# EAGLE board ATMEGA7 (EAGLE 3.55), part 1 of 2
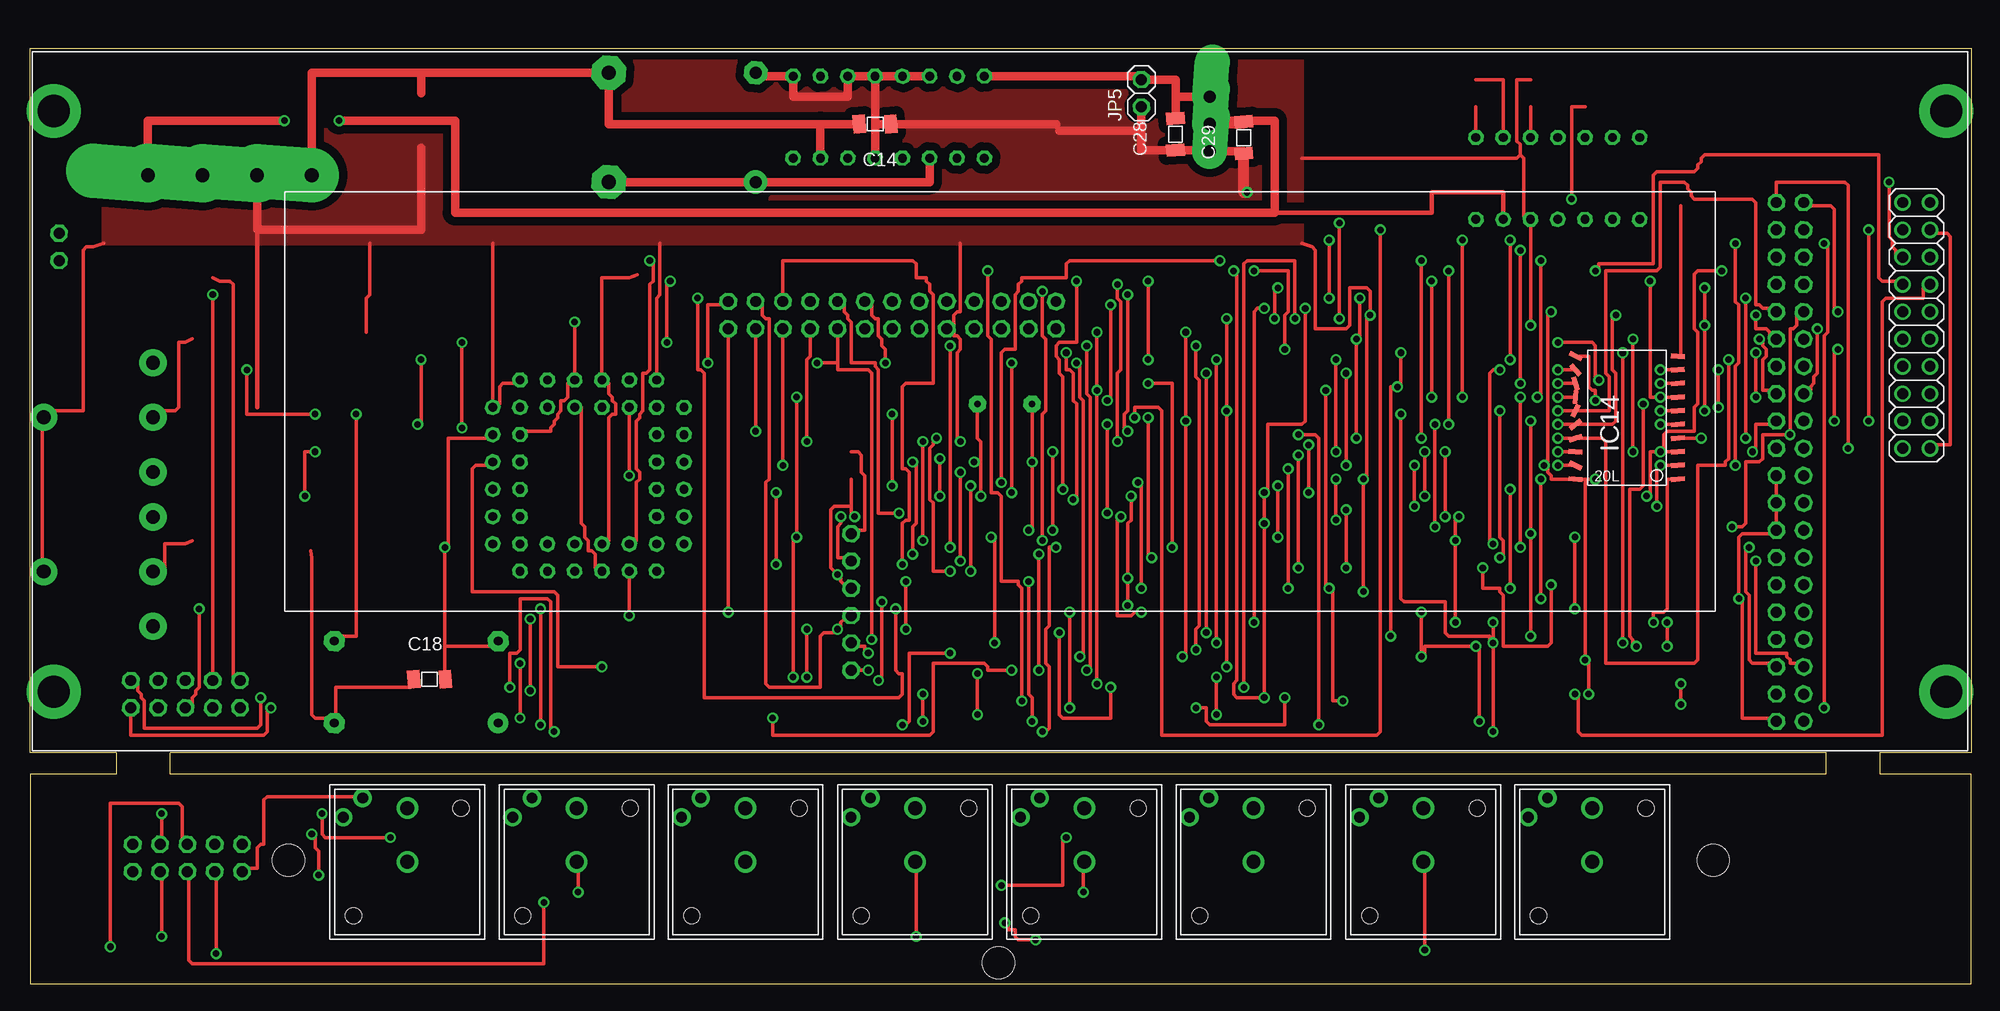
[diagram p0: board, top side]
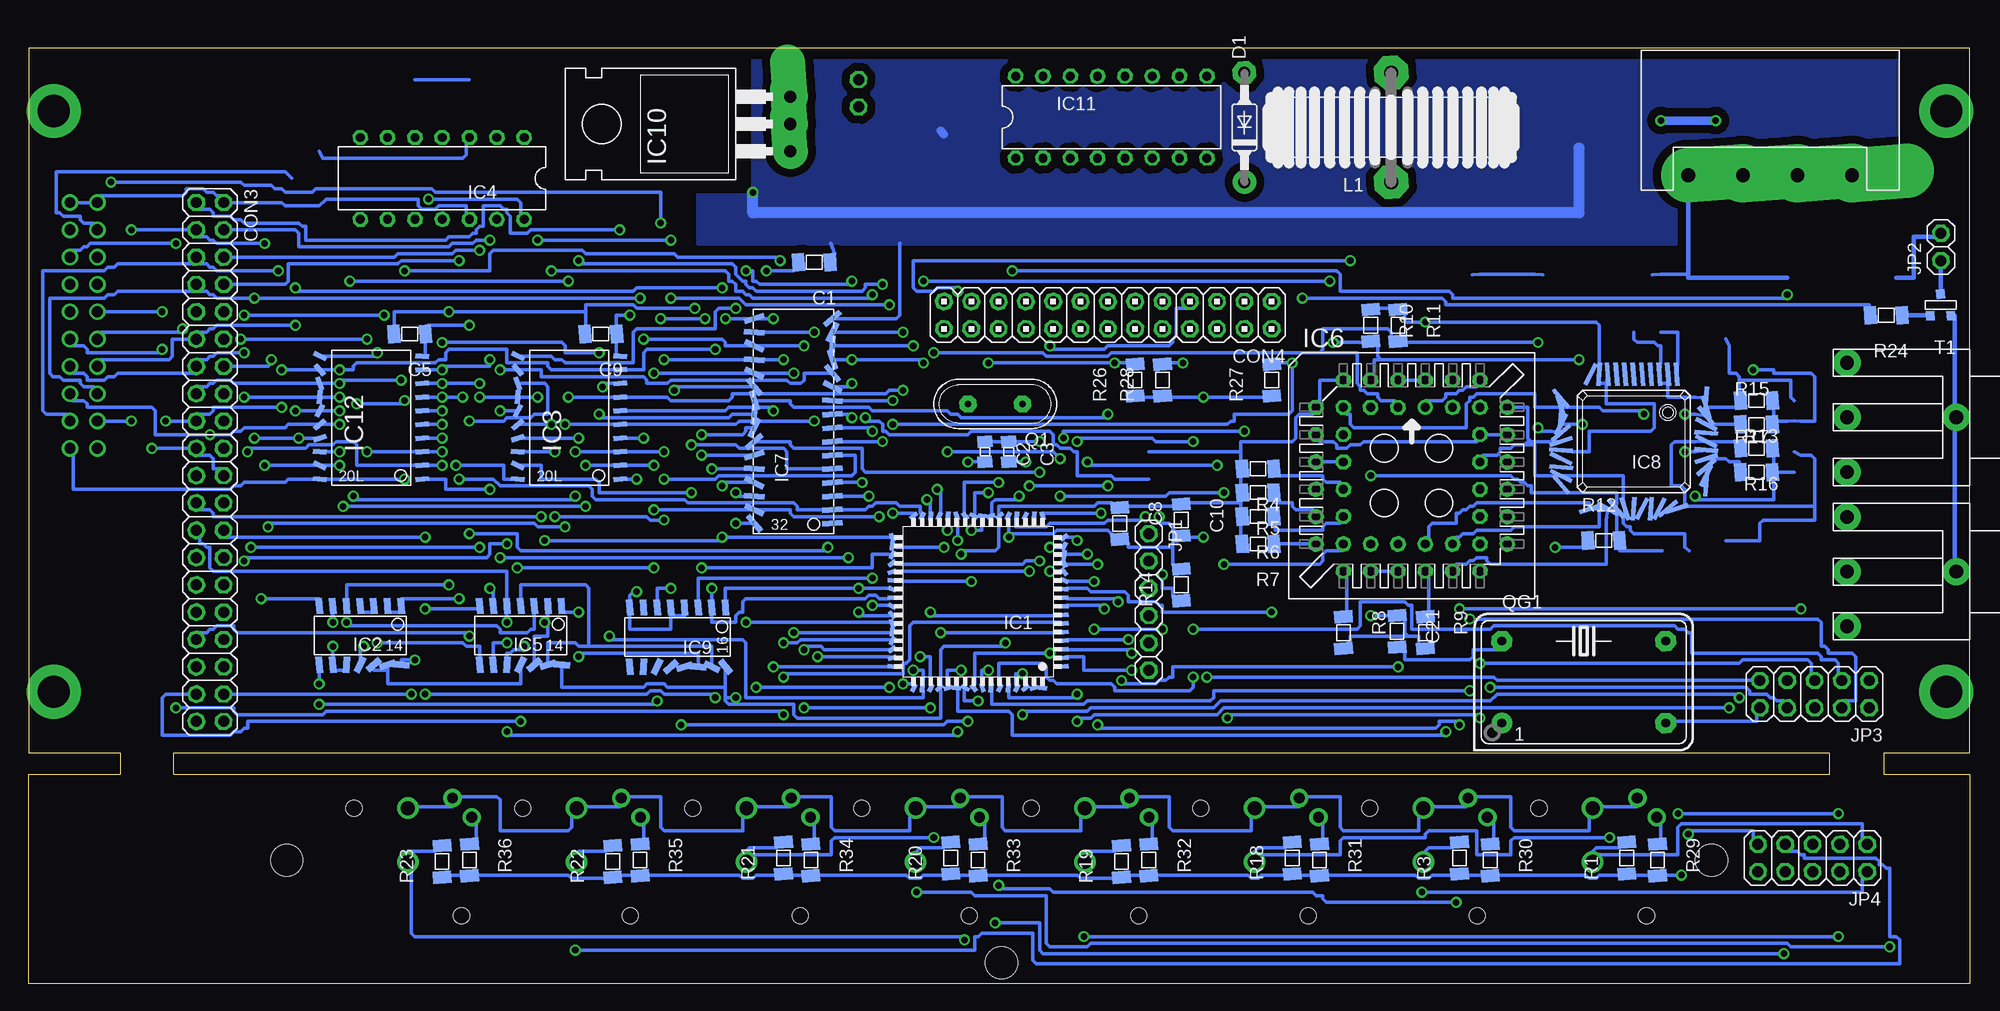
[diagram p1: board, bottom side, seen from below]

Size 180.5 x 87 mm. Coordinates in mm from the lower left corner, seen from the top.
Outline: 180.5,87 180.5,21.5 172,21.5 172,19.5 180.5,19.5 180.5,0 0,0 0,19.5 8,19.5 8,21.5 0,21.5 0,87 180.5,87
Outline: 167,21.5 13,21.5 13,19.5 167,19.5 167,21.5
Copper layers used: Top, Bottom
Holes 3 mm at 156.5,11.5 24,11.5 90.04,1.97
tRestrict: area 167,19.5 to 172,21.5; area 8,19.5 to 13,21.5
bRestrict: area 167,19.5 to 172,21.5; area 8,19.5 to 13,21.5

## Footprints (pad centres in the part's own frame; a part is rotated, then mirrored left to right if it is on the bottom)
06X = smd 1.143 x 1.702 rotated 4.4:  1.473,0 | smd 1.143 x 1.702 rotated 4.3:  -1.473,0
05 = smd 1.092 x 1.397 rotated 4.4:  0.94,0 | smd 1.092 x 1.397 rotated 4.3:  -0.94,0
06 = smd 1.143 x 1.702 rotated 4.4:  1.473,0 | smd 1.143 x 1.702 rotated 4.3:  -1.473,0
NCH = drill 1.27 pad 2.54 round:  -5.08,-6.35;  0,-6.35;  5.08,-6.35;  0,3.81
20 = drill 1.016 pad 1.6 octagon:  -24.13,-1.27;  -24.13,1.27;  -21.59,-1.27;  -21.59,1.27;  -19.05,-1.27;  -19.05,1.27;  -16.51,-1.27;  -16.51,1.27;  -13.97,-1.27;  -13.97,1.27;  -11.43,-1.27;  -11.43,1.27;  -8.89,-1.27;  -8.89,1.27;  -6.35,-1.27;  -6.35,1.27;  -3.81,-1.27;  -3.81,1.27;  -1.27,-1.27;  -1.27,1.27;  1.27,-1.27;  1.27,1.27;  3.81,-1.27;  3.81,1.27;  6.35,-1.27;  6.35,1.27;  8.89,-1.27;  8.89,1.27;  11.43,-1.27;  11.43,1.27;  13.97,-1.27;  13.97,1.27;  16.51,-1.27;  16.51,1.27;  19.05,-1.27;  19.05,1.27;  21.59,-1.27;  21.59,1.27;  24.13,-1.27;  24.13,1.27
13 = drill 1.016 pad 1.6 octagon:  -15.24,-1.27;  -15.24,1.27;  -12.7,-1.27;  -12.7,1.27;  -10.16,-1.27;  -10.16,1.27;  -7.62,-1.27;  -7.62,1.27;  -5.08,-1.27;  -5.08,1.27;  -2.54,-1.27;  -2.54,1.27;  0,-1.27;  0,1.27;  2.54,-1.27;  2.54,1.27;  5.08,-1.27;  5.08,1.27;  7.62,-1.27;  7.62,1.27;  10.16,-1.27;  10.16,1.27;  12.7,-1.27;  12.7,1.27;  15.24,-1.27;  15.24,1.27
5ZOLL = drill 1.27 pad 5.08 offset:  2.54,-7.62;  -2.54,-7.62;  -7.62,-7.62;  7.62,-7.62
D81 = drill 1.118 pad 2.159 round:  -5.08,0 | drill 1.118 pad 2.159 octagon:  5.08,0
10' = drill 3 pad 5 round:  82.79,26.29;  82.79,-27.71;  -93.21,-27.71;  -93.21,26.29 | drill 1.016 pad 1.524 round:  78.74,17.78;  81.28,17.78;  78.74,15.24;  81.28,15.24;  78.74,12.7;  81.28,12.7;  78.74,10.16;  81.28,10.16;  78.74,7.62;  81.28,7.62;  78.74,5.08;  81.28,5.08;  78.74,2.54;  81.28,2.54;  78.74,0;  81.28,0;  78.74,-2.54;  81.28,-2.54;  78.74,-5.08;  81.28,-5.08
FP64 = smd 0.813 x 0.406 rotated 4.3:  -8,6;  -8,-1.2 | smd 0.813 x 0.406 rotated 4.4:  -8,5.2 | smd 0.813 x 0.406 rotated 4.5:  -8,4.4 | smd 0.813 x 0.406 rotated 4.6:  -8,3.6;  8,-0.4 | smd 0.813 x 0.406 rotated 4.7:  -8,2.8;  -8,2 | smd 0.813 x 0.406 rotated 4.8:  -8,1.2 | smd 0.813 x 0.406 rotated 4.9:  -8,0.4 | smd 0.813 x 0.406 rotated 5:  -8,-0.4 | smd 0.813 x 0.406 rotated 26.8:  -8,-2 | smd 0.813 x 0.406 rotated 49.3:  -8,-2.8 | smd 0.813 x 0.406 rotated 71.8:  -8,-3.6 | smd 0.813 x 0.406 rotated 94.3:  -8,-4.4 | smd 0.813 x 0.406 rotated 116.8:  -8,-5.2 | smd 0.813 x 0.406 rotated 139.3:  -8,-6 | smd 0.406 x 0.813 rotated 161.8:  -6,-8 | smd 0.406 x 0.813 rotated 184.3:  -5.2,-8 | smd 0.406 x 0.813 rotated 206.8:  -4.4,-8 | smd 0.406 x 0.813 rotated 4.4:  -3.6,-8 | smd 0.406 x 0.813 rotated 26.9:  -2.8,-8 | smd 0.406 x 0.813 rotated 49.4:  -2,-8 | smd 0.406 x 0.813 rotated 71.9:  -1.2,-8 | smd 0.406 x 0.813 rotated 94.4:  -0.4,-8 | smd 0.406 x 0.813 rotated 116.9:  0.4,-8 | smd 0.406 x 0.813 rotated 139.4:  1.2,-8 | smd 0.406 x 0.813 rotated 161.9:  2,-8 | smd 0.406 x 0.813 rotated 184.4:  2.8,-8 | smd 0.406 x 0.813 rotated 206.9:  3.6,-8 | smd 0.406 x 0.813 rotated 4.5:  4.4,-8 | smd 0.406 x 0.813 rotated 27:  5.2,-8 | smd 0.406 x 0.813 rotated 49.5:  6,-8 | smd 0.813 x 0.406 rotated 72:  8,-6 | smd 0.813 x 0.406 rotated 94.5:  8,-5.2 | smd 0.813 x 0.406 rotated 117:  8,-4.4 | smd 0.813 x 0.406 rotated 139.5:  8,-3.6 | smd 0.813 x 0.406 rotated 162:  8,-2.8 | smd 0.813 x 0.406 rotated 184.5:  8,-2 | smd 0.813 x 0.406 rotated 207:  8,-1.2 | smd 0.813 x 0.406 rotated 27.1:  8,0.4 | smd 0.813 x 0.406 rotated 49.6:  8,1.2 | smd 0.813 x 0.406 rotated 72.1:  8,2 | smd 0.813 x 0.406 rotated 94.6:  8,2.8 | smd 0.813 x 0.406 rotated 117.1:  8,3.6 | smd 0.813 x 0.406 rotated 139.6:  8,4.4 | smd 0.813 x 0.406 rotated 162.1:  8,5.2 | smd 0.813 x 0.406 rotated 184.6:  8,6 | smd 0.406 x 0.813 rotated 207.1:  6,8 | smd 0.406 x 0.813 rotated 27.2:  4.4,8;  -3.6,8 | smd 0.406 x 0.813 rotated 4.7:  5.2,8;  -2.8,8 | smd 0.406 x 0.813 rotated 49.7:  3.6,8;  -4.4,8 | smd 0.406 x 0.813 rotated 72.2:  2.8,8;  -5.2,8 | smd 0.406 x 0.813 rotated 94.7:  2,8;  -6,8 | smd 0.406 x 0.813 rotated 117.2:  1.2,8 | smd 0.406 x 0.813 rotated 139.7:  0.4,8 | smd 0.406 x 0.813 rotated 162.2:  -0.4,8 | smd 0.406 x 0.813 rotated 184.7:  -1.2,8 | smd 0.406 x 0.813 rotated 207.2:  -2,8
-14 = smd 0.61 x 1.524 rotated 4.3:  -3.81,-2.794;  1.27,2.667 | smd 0.61 x 1.524 rotated 94.3:  -3.81,2.667 | smd 0.61 x 1.524 rotated 4.4:  -2.54,-2.794 | smd 0.61 x 1.524 rotated 4.5:  -1.27,-2.794 | smd 0.61 x 1.524 rotated 71.8:  -2.54,2.667 | smd 0.61 x 1.524 rotated 49.3:  -1.27,2.667 | smd 0.61 x 1.524 rotated 4.6:  0,-2.794 | smd 0.61 x 1.524 rotated 26.8:  0,2.667 | smd 0.61 x 1.524 rotated 4.7:  1.27,-2.794;  2.54,-2.794 | smd 0.61 x 1.524 rotated 5:  2.54,2.667 | smd 0.61 x 1.524 rotated 4.8:  3.81,-2.794 | smd 0.61 x 1.524 rotated 4.9:  3.81,2.667
-20L = smd 0.457 x 1.27 rotated 4.3:  -5.08,-5.131;  6.35,-5.131 | smd 0.457 x 1.27 rotated 4.4:  -3.81,-5.131;  -5.08,4.394 | smd 0.457 x 1.27 rotated 4.5:  -2.54,-5.131 | smd 0.457 x 1.27 rotated 4.6:  -1.27,-5.131 | smd 0.457 x 1.27 rotated 4.7:  0,-5.131;  1.27,-5.131 | smd 0.457 x 1.27 rotated 4.8:  2.54,-5.131 | smd 0.457 x 1.27 rotated 4.9:  3.81,-5.131 | smd 0.457 x 1.27 rotated 5:  5.08,-5.131 | smd 0.457 x 1.27 rotated 49.3:  5.08,4.394 | smd 0.457 x 1.27 rotated 26.8:  6.35,4.369 | smd 0.457 x 1.27 rotated 71.8:  3.81,4.394 | smd 0.457 x 1.27 rotated 94.3:  2.54,4.394 | smd 0.457 x 1.27 rotated 116.8:  1.27,4.394 | smd 0.457 x 1.27 rotated 139.3:  0,4.394 | smd 0.457 x 1.27 rotated 161.8:  -1.27,4.394 | smd 0.457 x 1.27 rotated 184.3:  -2.54,4.394 | smd 0.457 x 1.27 rotated 206.8:  -3.81,4.394
L-14 = drill 0.813 pad 1.397 octagon:  -7.62,-3.81;  -5.08,-3.81;  7.62,-3.81;  7.62,3.81;  -2.54,-3.81;  0,-3.81;  5.08,-3.81;  2.54,-3.81;  5.08,3.81;  2.54,3.81;  0,3.81;  -2.54,3.81;  -5.08,3.81;  -7.62,3.81
CC-S44 = drill 0.813 pad 1.397 round:  1.27,6.35 | drill 0.813 pad 1.397 octagon:  -1.27,8.89;  -1.27,6.35;  -3.81,8.89;  -3.81,6.35;  -6.35,8.89;  -8.89,6.35;  -6.35,6.35;  -8.89,3.81;  -6.35,3.81;  -8.89,1.27;  -6.35,1.27;  -8.89,-1.27;  -6.35,-1.27;  -8.89,-3.81;  -6.35,-3.81;  -8.89,-6.35;  -6.35,-8.89;  -6.35,-6.35;  -3.81,-8.89;  -3.81,-6.35;  -1.27,-8.89;  -1.27,-6.35;  1.27,-8.89;  1.27,-6.35;  3.81,-8.89;  3.81,-6.35;  6.35,-8.89;  8.89,-6.35;  6.35,-6.35;  8.89,-3.81;  6.35,-3.81;  8.89,-1.27;  6.35,-1.27;  8.89,1.27;  6.35,1.27;  8.89,3.81;  6.35,3.81;  8.89,6.35;  6.35,8.89;  6.35,6.35;  3.81,8.89;  3.81,6.35;  1.27,8.89
J-32/3 = smd 0.508 x 1.905 rotated 49.5:  -8.89,3.505 | smd 0.508 x 1.905 rotated 27:  -7.62,3.505 | smd 0.508 x 1.905 rotated 4.5:  -6.35,3.505;  -6.35,-3.759 | smd 0.508 x 1.905 rotated 206.9:  -5.08,3.505 | smd 0.508 x 1.905 rotated 184.4:  -3.81,3.505 | smd 0.508 x 1.905 rotated 26.9:  5.08,3.505 | smd 0.508 x 1.905 rotated 49.4:  3.81,3.505 | smd 0.508 x 1.905 rotated 71.9:  2.54,3.505 | smd 0.508 x 1.905 rotated 94.4:  1.27,3.505 | smd 0.508 x 1.905 rotated 49.3:  5.08,-3.759 | smd 0.508 x 1.905 rotated 26.8:  3.81,-3.759 | smd 0.508 x 1.905 rotated 4.3:  2.54,-3.759;  -8.89,-3.759 | smd 0.508 x 1.905 rotated 5:  1.27,-3.759 | smd 0.508 x 1.905 rotated 4.7:  -3.81,-3.759;  -2.54,-3.759 | smd 0.508 x 1.905 rotated 4.6:  -5.08,-3.759 | smd 0.508 x 1.905 rotated 4.4:  -7.62,-3.759;  6.35,3.505 | smd 0.508 x 1.905 rotated 71.8:  6.35,-3.759 | smd 0.508 x 1.905 rotated 161.9:  -2.54,3.505 | smd 0.508 x 1.905 rotated 116.9:  0,3.505 | smd 0.508 x 1.905 rotated 4.9:  0,-3.759 | smd 0.508 x 1.905 rotated 139.4:  -1.27,3.505 | smd 0.508 x 1.905 rotated 4.8:  -1.27,-3.759 | smd 0.508 x 1.905 rotated 94.3:  7.62,-3.759 | smd 0.508 x 1.905 rotated 206.8:  7.62,3.505 | smd 0.508 x 1.905 rotated 116.8:  8.89,-3.759 | smd 0.508 x 1.905 rotated 139.3:  10.16,-3.759 | smd 0.508 x 1.905 rotated 184.3:  8.89,3.505 | smd 0.508 x 1.905 rotated 161.8:  10.16,3.505
P-44 = smd 0.4 x 2.2 rotated 4.3:  -4,-6.25;  3.2,-6.25 | smd 0.4 x 2.2 rotated 4.4:  -3.2,-6.25 | smd 0.4 x 2.2 rotated 4.5:  -2.4,-6.25;  -1.6,6.25 | smd 0.4 x 2.2 rotated 4.6:  -1.6,-6.25 | smd 0.4 x 2.2 rotated 4.7:  -0.8,-6.25;  0,-6.25 | smd 0.4 x 2.2 rotated 4.8:  0.8,-6.25 | smd 0.4 x 2.2 rotated 4.9:  1.6,-6.25 | smd 0.4 x 2.2 rotated 5:  2.4,-6.24 | smd 0.4 x 2.2 rotated 26.8:  4,-6.25 | smd 0.4 x 2.2 rotated 72:  -4,6.25 | smd 0.4 x 2.2 rotated 49.5:  -3.2,6.25 | smd 0.4 x 2.2 rotated 27:  -2.4,6.25 | smd 0.4 x 2.2 rotated 206.9:  -0.8,6.25 | smd 0.4 x 2.2 rotated 184.4:  0,6.25 | smd 0.4 x 2.2 rotated 161.9:  0.8,6.25 | smd 0.4 x 2.2 rotated 139.4:  1.6,6.25 | smd 0.4 x 2.2 rotated 116.9:  2.4,6.26 | smd 0.4 x 2.2 rotated 94.4:  3.2,6.25 | smd 0.4 x 2.2 rotated 71.9:  4,6.25 | smd 2.2 x 0.4 rotated 49.3:  6.75,-4 | smd 2.2 x 0.4 rotated 71.8:  6.75,-3.2 | smd 2.2 x 0.4 rotated 94.3:  6.75,-2.4 | smd 2.2 x 0.4 rotated 116.8:  6.75,-1.6 | smd 2.2 x 0.4 rotated 139.3:  6.75,-0.8 | smd 2.2 x 0.4 rotated 161.8:  6.75,0 | smd 2.2 x 0.4 rotated 184.3:  6.75,0.8 | smd 2.2 x 0.4 rotated 206.8:  6.75,1.6 | smd 2.2 x 0.4 rotated 4.4:  6.74,2.4 | smd 2.2 x 0.4 rotated 26.9:  6.75,3.2 | smd 2.2 x 0.4 rotated 49.4:  6.75,4 | smd 2.2 x 0.4 rotated 94.6:  -6.75,-4 | smd 2.2 x 0.4 rotated 72.1:  -6.75,-3.2 | smd 2.2 x 0.4 rotated 49.6:  -6.75,-2.4 | smd 2.2 x 0.4 rotated 27.1:  -6.75,-1.6 | smd 2.2 x 0.4 rotated 4.6:  -6.75,-0.8 | smd 2.2 x 0.4 rotated 207:  -6.75,0 | smd 2.2 x 0.4 rotated 184.5:  -6.75,0.8 | smd 2.2 x 0.4 rotated 162:  -6.75,1.6 | smd 2.2 x 0.4 rotated 139.5:  -6.76,2.4 | smd 2.2 x 0.4 rotated 117:  -6.75,3.2 | smd 2.2 x 0.4 rotated 94.5:  -6.75,4
-16 = smd 0.61 x 1.524 rotated 4.3:  -3.81,-2.819;  3.81,2.692 | smd 0.61 x 1.524 rotated 139.3:  -3.81,2.692 | smd 0.61 x 1.524 rotated 4.4:  -2.54,-2.819 | smd 0.61 x 1.524 rotated 4.5:  -1.27,-2.819 | smd 0.61 x 1.524 rotated 116.8:  -2.54,2.692 | smd 0.61 x 1.524 rotated 94.3:  -1.27,2.692 | smd 0.61 x 1.524 rotated 4.6:  0,-2.819 | smd 0.61 x 1.524 rotated 71.8:  0,2.692 | smd 0.61 x 1.524 rotated 4.7:  1.27,-2.819;  2.54,-2.819 | smd 0.61 x 1.524 rotated 49.3:  1.27,2.692 | smd 0.61 x 1.524 rotated 4.8:  3.81,-2.819 | smd 0.61 x 1.524 rotated 26.8:  2.54,2.692 | smd 0.61 x 1.524 rotated 4.9:  5.08,-2.819 | smd 0.61 x 1.524 rotated 5:  5.08,2.692
220H = drill 1.118 pad 3.251 offset:  -2.54,-6.35;  0,-6.35;  2.54,-6.35
L16 = drill 0.813 pad 1.397 octagon:  -8.89,-3.81;  -6.35,-3.81;  6.35,-3.81;  8.89,-3.81;  -3.81,-3.81;  -1.27,-3.81;  3.81,-3.81;  1.27,-3.81;  8.89,3.81;  6.35,3.81;  3.81,3.81;  1.27,3.81;  -1.27,3.81;  -3.81,3.81;  -6.35,3.81;  -8.89,3.81
6_X = drill 1.016 pad 1.6 octagon:  -6.35,0;  -3.81,0;  -1.27,0;  1.27,0;  3.81,0;  6.35,0
02 = drill 1.016 pad 1.6 octagon:  -1.27,0;  1.27,0
05'' = drill 1.016 pad 1.6 octagon:  -5.08,-1.27;  -5.08,1.27;  -2.54,-1.27;  -2.54,1.27;  0,-1.27;  0,1.27;  2.54,-1.27;  2.54,1.27;  5.08,-1.27;  5.08,1.27
023 = drill 1.321 pad 3.15 octagon:  -7.62,0;  2.54,0
_X = drill 0.61 pad 1.6 octagon:  -2.54,0;  2.54,0
L14S = drill 0.813 pad 1.905 round:  -7.62,-3.81 | drill 0.813 pad 1.905 octagon:  7.62,-3.81;  7.62,3.81;  -7.62,3.81
G5560 = drill 1.3 pad 2 round:  0,0;  0,5 | drill 1 pad 1.7 round:  -4.15,5.95;  -5.95,4.15 | hole 1.5: 5,5; -5,-5
T-23 = smd 0.787 x 0.889 rotated 4.4:  0.991,1.016 | smd 0.787 x 0.889 rotated 4.3:  -0.94,1.016 | smd 0.787 x 0.889 rotated 4.5:  0.025,-1.016

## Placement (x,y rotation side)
C1  100n  [06X]  107.45,67.12 180 bottom
C2  30p  [05]  91.58,49.5 270 bottom
C3  30p  [05]  89.35,49.5 270 bottom
C4  10æ/25V  [-2,5L]  139.52,84.11 270 bottom
C5  100n  [06X]  145.07,60.45 180 bottom
C6  10æ/25v  [-2,5L]  144.6,81.56 90 bottom
C7  10æ/25V  [-2,5L]  134.44,81.56 90 bottom
C8  100n  [06X]  79.03,42.83 270 bottom
C9  100n  [06X]  127.29,60.45 180 bottom
C10  100n  [06X]  73.32,43.15 270 bottom
C11  ELC-2,5L  [-2,5L]  28.61,40.28 0 bottom
C12  10æ  [-2,5L]  76.33,46.96 90 bottom
C13  330æ/16V  [-5]  36.33,80.3 270 bottom
C14  100n  [06X]  78.56,79.98 180 top
C17  10æ  [-2,5L]  28.71,60.6 180 bottom
C18  100n  [06]  37.12,28.33 0 top
C21  100n  [06X]  53.24,32.8 270 bottom
C22  330p  [05']  16.33,53.31 90 bottom
C24  330p  [05']  16.33,48.55 90 bottom
C25  1æ  [7,5]  18.87,60 0 bottom
C26  1æ  [7,5]  18.87,41.2 0 bottom
C28  100n  [06]  106.5,79.03 90 top
C29  100n  [06]  112.85,78.71 90 top
C31  330æ/16V  [-5]  95.7,81.88 270 bottom
CON1  CINCHF  [NCH]  5.05,38.34 270 bottom
CON2  CINCHF  [NCH]  5.05,52.7 270 bottom
CON3  IDEBUS  [20]  163.65,48.55 270 bottom
CON4  SUBD25  [13]  80.14,62.2 180 bottom
CON6  525ZOLL  [5ZOLL]  18.55,82.83 0 bottom
D1  1N5819  [D81]  67.44,79.66 90 bottom
D2  1N4148  [10]  34.6,65.95 180 bottom
D3  1N4148  [10]  51.34,65.96 180 bottom
DIS1  240X64  [10']  95.39,54.9 0 top
IC1  MEGA103  [FP64]  92.21,35.53 180 bottom
IC2  7400  [-14]  149.68,32.35 180 bottom
IC3  74573  [-20L]  130.63,52.04 90 bottom
IC4  MAX231  [L-14]  142.05,74.92 180 bottom
IC5  7432  [-14]  134.75,32.35 180 bottom
IC6  MAS3507D  [CC-S44]  51.89,47.27 0 bottom
IC7  628128P  [J-32/3]  109.51,51.72 90 bottom
IC8  DAC3550A  [P-44]  31.25,50.45 180 bottom
IC9  74138  [-16]  119.52,32.19 180 bottom
IC10  LT1086-12 5A  [220H]  116.02,79.98 90 bottom
IC11  LM2575N-05  [L16]  79.83,80.61 0 bottom
IC12  74574  [-20L]  149.04,52.04 90 bottom
IC14  74574  [-20L]  148.09,52.04 90 top
JP1  Prog-Con  [6_X]  76.33,35.53 270 bottom
JP2  LIGHT  [02]  2.67,68.55 90 bottom
JP3  PINHD-2X5  [05'']  14.42,26.95 180 bottom
JP4  PINHD-2X5  [05'']  14.61,11.71 180 bottom
JP5  Power  [02]  103.32,82.83 90 top
L1  220æH  [023]  53.79,82.2 90 bottom
Q1  6MHz  [_X]  90.62,53.94 180 bottom
QG1  XO-14  [L14S]  35.89,28.07 0 bottom
R1  4k7  [06]  31.88,11.71 90 bottom
R2  2K5  [-10S]  154.75,74.92 90 bottom
R3  4k7  [06]  47.44,11.71 90 bottom
R4  10k  [06X]  66.17,47.91 180 bottom
R5  10k  [06X]  66.17,45.69 180 bottom
R6  10k  [06X]  66.17,43.47 180 bottom
R7  10k  [06X]  66.17,40.93 180 bottom
R8  10k  [06X]  58.24,32.67 270 bottom
R9  10k  [06X]  50.62,32.67 270 bottom
R10  4K7  [06X]  55.7,61.25 270 bottom
R11  4K7  [06X]  53.16,61.25 270 bottom
R12  10k  [06X]  34.03,41.24 0 bottom
R13  15k  [06X]  19.82,54.27 180 bottom
R14  10k  [06X]  73.32,37.11 90 bottom
R15  15k  [06X]  19.82,52.04 0 bottom
R16  15k  [06X]  19.82,49.82 180 bottom
R17  15k  [06X]  19.82,47.6 0 bottom
R18  4k7  [06]  63,11.71 90 bottom
R19  4k7  [06]  78.88,11.4 90 bottom
R20  4k7  [06]  94.75,11.71 90 bottom
R21  4k7  [06]  110.31,11.71 90 bottom
R22  4k7  [06]  126.18,11.4 90 bottom
R23  4k7  [06]  142.06,11.4 90 bottom
R24  4k7  [06]  7.76,62.2 180 bottom
R25  10R/0,5W  [10]  11.88,65.69 180 bottom
R26  4k7  [06X]  77.61,56.16 90 bottom
R27  4k7  [06X]  64.91,56.16 90 bottom
R28  4k7  [06X]  75.06,56.16 90 bottom
R29  180R  [06X]  29.03,11.53 270 bottom
R30  180R  [06X]  44.59,11.53 270 bottom
R31  180R  [06X]  60.46,11.53 270 bottom
R32  180R  [06X]  76.33,11.53 270 bottom
R33  180R  [06X]  92.21,11.53 270 bottom
R34  180R  [06X]  107.77,11.53 270 bottom
R35  180R  [06X]  123.64,11.53 270 bottom
R36  180R  [06X]  139.52,11.53 270 bottom
SW1  13G5560  [G5560]  35.05,11.35 0 top
SW2  13G5560  [G5560]  50.8,11.35 0 top
SW3  13G5560  [G5560]  66.5,11.35 0 top
SW4  13G5560  [G5560]  82.28,11.35 0 top
SW5  13G5560  [G5560]  98.03,11.35 0 top
SW6  13G5560  [G5560]  113.75,11.35 0 top
SW7  13G5560  [G5560]  129.55,11.35 0 top
SW8  13G5560  [G5560]  145.25,11.35 0 top
T1  BC547  [T-23]  2.67,63.15 180 bottom

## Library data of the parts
C1-C3 C5 C8-C10 C14 C18 C21 C28 C29 R1 R3-R24 R26-R36 T1 = SMD
C4 C6 C7 C11-C13 C17 C22 C24-C26 C31 D2 D3 R2 R25 = DISCRETE
CON1 CON2 = cinch
CON3 CON4 JP1-JP5 = PINHEAD
CON6 = PCPOWER
D1 = DIODE
DIS1 = DISPLAY
IC1 = ATMEL
IC2 IC3 IC5 IC7-IC9 IC12 = SMD-IC
IC4 IC6 = IC
IC10 = LINEAR
IC11 = national
IC14 = 74XXSMD
L1 = spule
Q1 = SPECIAL
QG1 = QUARTZ
SW1-SW8 = taster

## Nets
0V: JP4. SW1. SW2. SW3. SW4. SW5. SW6. SW7. SW8.
+3V: C18. C21. D3. IC6. IC8. QG1. R10. R11. R12.
+5V: JP4. R1. R3. R18. R19. R20. R21. R22. R23. R29. R30. R31. R32. R33. R34. R35. R36.
+12V: C29. CON6. IC4. IC10.
+15V: C28. C31. IC10. IC11. JP5.
-12V: C4. IC4. R2.
A0: CON3. IC3. IC7.
A1: CON3. IC3. IC7.
A2: CON3. IC3. IC7.
A3: IC3. IC7.
A4: IC3. IC7.
A5: IC3. IC7.
A6: IC3. IC7.
A7: IC3. IC7.
A8: IC1. IC7.
A9: IC1. IC7.
A10: IC1. IC7.
A11: IC1. IC7.
A12: IC1. IC7. IC9.
A13: IC1. IC7. IC9.
A14: IC1. IC7. IC9.
A15: IC1. IC2. IC7.
A16: IC1. IC2. IC7.
AD0: CON3. DIS1. IC1. IC3. IC7. IC12. IC14.
AD1: CON3. DIS1. IC1. IC3. IC7. IC12. IC14.
AD2: CON3. DIS1. IC1. IC3. IC7. IC12. IC14.
AD3: CON3. DIS1. IC1. IC3. IC7. IC12. IC14.
AD4: CON3. DIS1. IC1. IC3. IC7. IC12. IC14.
AD5: CON3. DIS1. IC1. IC3. IC7. IC12. IC14.
AD6: CON3. DIS1. IC1. IC3. IC7. IC12. IC14.
AD7: CON3. DIS1. IC1. IC3. IC7. IC12. IC14.
CLKI: IC6. IC8. QG1.
CLKO: IC6.
DEMAND: IC1. IC6.
GND: C1. C2. C3. C4. C5. C6. C8. C9. C10. C11. C12. C13. C14. C17. C18. C21. C28. C29. C31. CON1. CON2. CON3. CON4. CON6. D1. DIS1. IC1. IC2. IC3. IC4. IC5. IC6. IC7. IC8. IC9. IC10. IC11. IC12. IC14. JP1. JP3. JP5. QG1. R2. R4. R5. R6. R7. R8. R9. T1.
IDE_CSHI: IC5. IC9.
IDE_CSLO: CON3. IC5. IC9.
IDE_D8: CON3. IC12. IC14.
IDE_D9: CON3. IC12. IC14.
IDE_D10: CON3. IC12. IC14.
IDE_D11: CON3. IC12. IC14.
IDE_D12: CON3. IC12. IC14.
IDE_D13: CON3. IC12. IC14.
IDE_D14: CON3. IC12. IC14.
IDE_D15: CON3. IC12. IC14.
LCD_CD: DIS1. IC1.
LCD_CS: DIS1. IC1.
LCDLIGHT: IC1. R24.
LPTACK: CON4. IC1. R28.
LPTCLK: CON4. IC1. R27.
LPTD0: CON4. IC1.
LPTD1: CON4. IC1. JP1.
LPTD2: CON4. IC1.
LPTD3: CON4. IC1.
LPTD4: CON4. IC1.
LPTD5: CON4. IC1.
LPTD6: CON4. IC1.
LPTD7: CON4. IC1.
LPTHALT: CON4. IC1. R26.
MCU_RD: CON3. IC1. IC5. IC7.
MCU_RESE: C12. CON3. DIS1. IC1. JP1. R14.
MCU_WR: CON3. IC1. IC5. IC7.
MEM_/CS1: IC2. IC7. IC9.
MEM_CS2: IC2.
N$1: DIS1. R2.
N$2: IC1. JP1.
N$3: IC1. JP1.
N$4: IC1. IC3.
N$5: C7. IC4.
N$6: C7. IC4.
N$7: C6. IC4.
N$8: IC6. R4.
N$9: C2. IC1. Q1.
N$10: C3. IC1. Q1.
N$11: IC5. IC12.
N$12: IC5. IC12.
N$13: D1. IC11. L1.
N$14: IC6. R5.
N$15: IC6. R6.
N$16: IC6. R7.
N$17: IC5. IC14.
N$18: C22. IC8. R13. R15.
N$19: IC6. R8.
N$20: IC6. R9.
N$21: C24. IC8. R16. R17.
N$22: C24. C26. IC8. R16.
N$23: IC8. R15.
N$24: IC6.
N$25: C22. C25. IC8. R13.
N$26: IC8. R17.
N$27: C26. CON1.
N$28: C25. CON2.
N$29: IC2.
N$30: IC2. IC14.
N$31: C17. IC8.
N$32: D2. D3.
N$33: JP2. R25.
N$34: IC2. IC5.
N$35: JP2. T1.
N$36: R29. SW1.
N$37: R24. T1.
N$38: R30. SW2.
N$39: R31. SW3.
N$40: R32. SW4.
N$41: R33. SW5.
N$42: R34. SW6.
N$43: R35. SW7.
N$44: R36. SW8.
PER_RD: DIS1. IC1.
PER_WR: DIS1. IC1.
RESET: C11. IC6. IC8. R12.
SCL: IC1. IC6. IC8. R10.
SDA: IC1. IC6. IC8. R11.
SIC: IC1. IC6.
SID: IC1. IC6.
SOC: IC6. IC8.
SOD: IC6. IC8.
SOI: IC6. IC8.
TASTER0: IC1. JP3.
TASTER1: IC1. JP3.
TASTER2: IC1. JP3.
TASTER3: IC1. JP3.
TASTER4: IC1. JP3.
TASTER5: IC1. JP3.
TASTER6: IC1. JP3.
TASTER7: IC1. JP3.
TASTERX0: JP4. R1. SW1.
TASTERX1: JP4. R3. SW2.
TASTERX2: JP4. R18. SW3.
TASTERX3: JP4. R19. SW4.
TASTERX4: JP4. R20. SW5.
TASTERX5: JP4. R21. SW6.
TASTERX6: JP4. R22. SW7.
TASTERX7: JP4. R23. SW8.
VCC: C1. C5. C8. C9. C10. C13. C14. CON3. CON6. D2. DIS1. IC1. IC2. IC3. IC5. IC7. IC9. IC11. IC12. IC14. JP1. JP3. L1. R14. R25. R26. R27. R28.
